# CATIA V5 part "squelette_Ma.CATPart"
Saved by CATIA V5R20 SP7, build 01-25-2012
Part number: squelette_Ma
Publications: "barre_Ma", "axe.pivot.M", "Plan.pivot.M"
Bounding box of the stored display mesh (mm): x -22 to -2, y -67.987 to 0, z 21.983 to 25.5
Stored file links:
  F:\IAO_Renouveau\squelette_Ma.CATPart
  F:\IAO_Renouveau\squelette.CATProduct
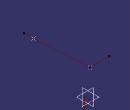
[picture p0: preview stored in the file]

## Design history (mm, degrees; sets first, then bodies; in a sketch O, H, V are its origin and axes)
Set1
  Point1 "M": linked copy from another document
  Point2 "machoires.a": linked copy from another document
  Plane1 "plan.-2": linked copy from another document
Set2
  Line1 "barre_Ma": type PtPt, FirstPoint Point1, SecondPoint Point2, End 10
  Line2 "axe.pivot.M": type Normal, RefPoint Point1, RefSkin Plane1, Start 0, End 20
  Plane2 "Plan.pivot.M": type Offset, RefPlane Plane1, Offset 0
Body1 (main body)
